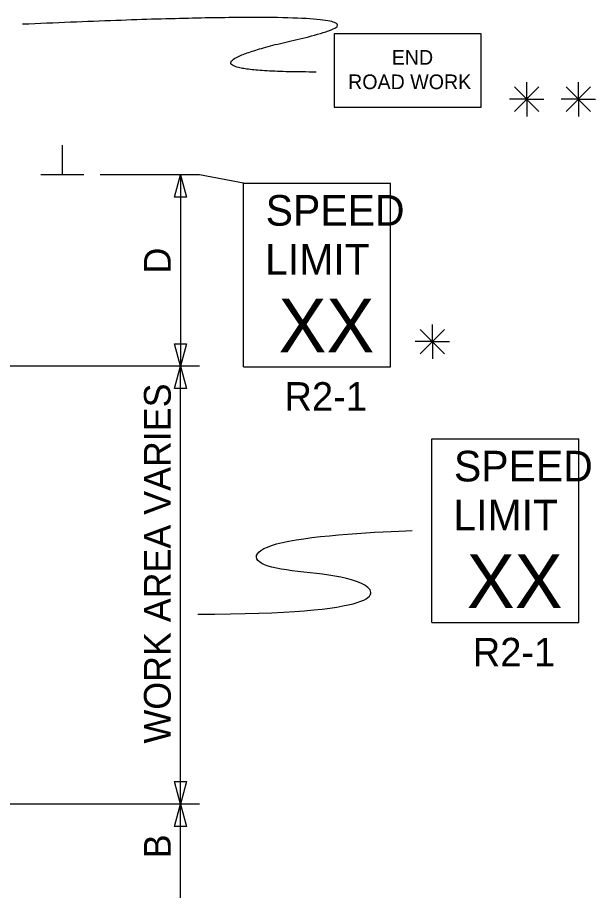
# Model space of a CAD drawing. Extents: x 16590 to 19508, y 5703 to 6974.
# Drawn here: x 18006.3 to 18157.5, y 6695.4 to 6923.7 of the extents above; entities that cross this region are included whole.
import ezdxf

# ---------------------------------------------------------------- set-up
doc = ezdxf.new("R2010")
doc.units = 0
doc.layers.add('TRAFFIC_SIGNS_PR', color=7, linetype='Continuous')
doc.layers.add('TYPICAL_TEXT_DIMEN_PR', color=7, linetype='Continuous')

msp = doc.modelspace()

# ---------------------------------------------------------------- linework, layer by layer
at = {"layer": 'TRAFFIC_SIGNS_PR'}
for p, q in [((18065.45, 6880.37), (18103.9, 6880.37)), ((18065.45, 6832.31), (18065.45, 6880.37)), ((18103.9, 6832.31), (18103.9, 6880.37)), ((18065.45, 6832.31), (18103.9, 6832.31)), ((18114.69, 6813.49), (18153.14, 6813.49)), ((18114.69, 6765.44), (18114.69, 6813.49)), ((18153.14, 6765.44), (18153.14, 6813.49)), ((18114.69, 6765.44), (18153.14, 6765.44))]:
    msp.add_line(p, q, dxfattribs=at)
msp.add_lwpolyline([(18089.17, 6900.17), (18127.62, 6900.17), (18127.62, 6919.4), (18089.17, 6919.4)], close=True, dxfattribs=at)
msp.add_open_spline([(18084.45, 6909.4), (18041.94, 6909.4), (18118.46, 6926.82), (18007.67, 6921.88)], degree=2, dxfattribs=at)
at = {"layer": 'TYPICAL_TEXT_DIMEN_PR'}
for p, q in [((18139.51, 6902.3), (18139.51, 6906.75)), ((18153.01, 6902.3), (18153.01, 6906.75)), ((18136.32, 6905.49), (18142.69, 6899.11)), ((18142.69, 6905.49), (18136.32, 6899.11)), ((18156.2, 6905.49), (18149.82, 6899.11)), ((18149.83, 6905.49), (18156.2, 6899.11)), ((18139.51, 6902.3), (18134.97, 6902.3)), ((18139.51, 6902.3), (18142.69, 6902.3)), ((18139.51, 6902.3), (18143.98, 6902.3)), ((18139.51, 6902.3), (18139.51, 6897.8)), ((18153.01, 6902.3), (18148.48, 6902.3)), ((18153.01, 6902.3), (18156.2, 6902.3)), ((18153.01, 6902.3), (18157.49, 6902.3)), ((18153.01, 6902.3), (18153.01, 6897.8)), ((18018.08, 6882.5), (18018.08, 6890.28)), ((18023.71, 6882.5), (18012.46, 6882.5)), ((18053.96, 6882.5), (18027.96, 6882.5)), ((18047.39, 6876.64), (18048.96, 6882.5)), ((18048.96, 6882.5), (18048.96, 6832.5)), ((18048.96, 6882.5), (18050.53, 6876.64)), ((18065.45, 6880.37), (18053.96, 6882.5)), ((18048.96, 6876.64), (18047.39, 6876.64)), ((18050.53, 6876.64), (18048.96, 6876.64)), ((18114.85, 6838.9), (18114.85, 6843.36)), ((18111.66, 6842.09), (18118.03, 6835.72)), ((18118.03, 6842.09), (18111.66, 6835.72)), ((18048.96, 6832.5), (18047.39, 6838.36)), ((18047.39, 6838.36), (18048.96, 6838.36)), ((18048.96, 6838.36), (18050.53, 6838.36)), ((18050.53, 6838.36), (18048.96, 6832.5)), ((18114.85, 6838.9), (18110.31, 6838.9)), ((18114.85, 6838.9), (18118.03, 6838.9)), ((18114.85, 6838.9), (18119.32, 6838.9)), ((18114.85, 6838.9), (18114.85, 6834.4)), ((18053.96, 6832.5), (17971.56, 6832.5)), ((18047.39, 6826.64), (18048.96, 6832.5)), ((18048.96, 6717.96), (18048.96, 6832.5)), ((18048.96, 6832.5), (18050.53, 6826.64)), ((18048.96, 6826.64), (18047.39, 6826.64)), ((18050.53, 6826.64), (18048.96, 6826.64)), ((18048.96, 6717.96), (18047.39, 6723.83)), ((18047.39, 6723.83), (18048.96, 6723.83)), ((18048.96, 6723.83), (18050.53, 6723.83)), ((18050.53, 6723.83), (18048.96, 6717.96)), ((18053.96, 6717.96), (17971.56, 6717.96)), ((18047.39, 6712.1), (18048.96, 6717.96)), ((18048.96, 6688.54), (18048.96, 6717.96)), ((18048.96, 6717.96), (18050.53, 6712.1)), ((18048.96, 6712.1), (18047.39, 6712.1)), ((18050.53, 6712.1), (18048.96, 6712.1))]:
    msp.add_line(p, q, dxfattribs=at)
msp.add_open_spline([(18053.49, 6767.65), (18101.95, 6767.65), (18101.95, 6778.4), (18067.04, 6778.4), (18067.04, 6787.45), (18101.24, 6789.22), (18109.53, 6789.51)], degree=3, dxfattribs=at)

# ---------------------------------------------------------------- texts
at = {"layer": 'TRAFFIC_SIGNS_PR'}
for s, height, p in [('END', 3.836, (18104.19, 6911.32)), ('ROAD WORK', 3.836, (18092.78, 6904.92)), ('SPEED', 8.01, (18071.23, 6869.22)), ('LIMIT', 8.01, (18071.07, 6856.4)), ('XX', 14.048, (18074.58, 6836.07)), ('R2-1', 7.449, (18076.14, 6820.85)), ('SPEED', 8.01, (18120.46, 6802.34)), ('LIMIT', 8.01, (18120.3, 6789.53)), ('XX', 14.048, (18123.81, 6769.2)), ('R2-1', 7.449, (18125.38, 6753.98))]:
    msp.add_text(s, height=height, dxfattribs=at).set_placement(p)
at = {"layer": 'TYPICAL_TEXT_DIMEN_PR'}
for s, p in [('D', (18046.4, 6856.72)), ('WORK AREA VARIES', (18046.4, 6733.81)), ('B', (18046.4, 6703.8))]:
    msp.add_text(s, height=7, rotation=90, dxfattribs=at).set_placement(p)

doc.saveas('drawing.dxf')
